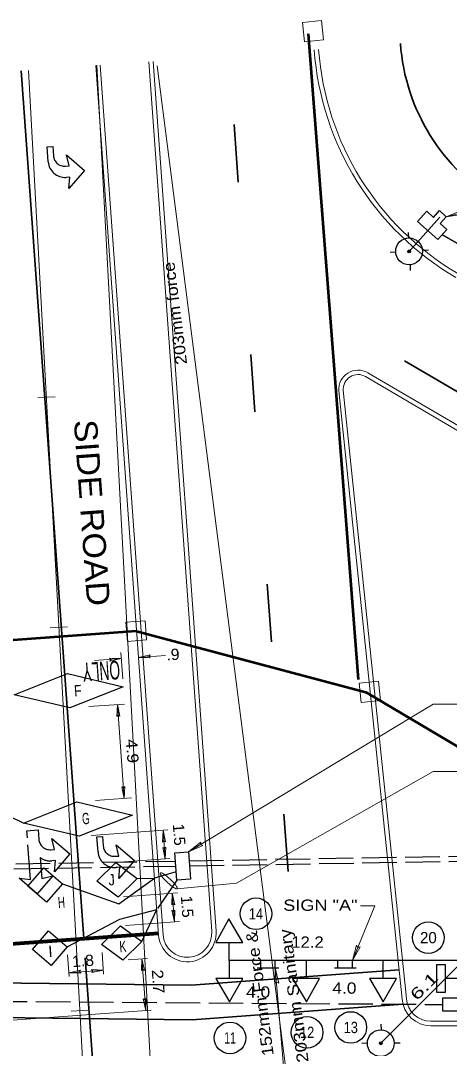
# Model space of a CAD drawing. Extents: x 168203 to 169863, y 223196 to 223870.
# Drawn here: x 168345.6 to 168367.9, y 223652.3 to 223705.8 of the extents above; entities that cross this region are included whole.
import ezdxf
from ezdxf.enums import TextEntityAlignment as Align

# ---------------------------------------------------------------- set-up
doc = ezdxf.new("R2010")
doc.units = 0
doc.header["$LTSCALE"] = 0.3
doc.header["$PDMODE"] = 32
doc.header["$PDSIZE"] = 0.15
doc.linetypes.add('LONG_DASH_SHORT_DASH', pattern=[9.9, 6, -1.2, 1.5, -1.2])
doc.linetypes.add('LONG_DASHED', pattern=[7.5, 6, -1.5])
for name, color, linetype, lineweight in [('1', 7, 'Continuous', 13), ('11', 7, 'Continuous', 13), ('23', 7, 'Continuous', 25), ('31', 7, 'Continuous', 25), ('36', 7, 'Continuous', 35), ('5', 7, 'Continuous', 25), ('7', 7, 'Continuous', 25), ('9', 7, 'Continuous', 13)]:
    doc.layers.add(name, color=color, linetype=linetype, lineweight=lineweight)

msp = doc.modelspace()

# ---------------------------------------------------------------- linework, layer by layer
at = {"layer": '1'}
for p, q in [((168352.2908, 223703.665), (168355.5629, 223658.3883)), ((168352.5202, 223703.6815), (168355.7923, 223658.4049)), ((168349.7975, 223634.2675), (168346.0287, 223703.2124)), ((168352.8001, 223658.1888), (168349.528, 223703.4653)), ((168353.0296, 223658.2052), (168349.7575, 223703.4819)), ((168363.5687, 223687.27), (168399.2919, 223666.2921)), ((168363.6851, 223687.4684), (168399.4139, 223666.4872)), ((168365.473, 223654.8595), (168362.1813, 223686.534)), ((168365.7018, 223654.8832), (168362.4101, 223686.5577)), ((168346.5111, 223686.1736), (168347.4098, 223686.2226)), ((168347.1644, 223674.1914), (168348.0631, 223674.2404)), ((168348.256, 223654.2212), (168349.1547, 223654.2702)), ((168389.7958, 223653.6976), (168366.9691, 223653.6976)), ((168389.7958, 223653.4676), (168366.9691, 223653.4676))]:
    msp.add_line(p, q, dxfattribs=at)
for points in [[(168360.2873, 223705.7061), (168361.2849, 223705.8098), (168361.3886, 223704.8122), (168360.391, 223704.7085)], [(168351.1029, 223674.483), (168352.1033, 223674.5553), (168352.1756, 223673.5549), (168351.1752, 223673.4826)], [(168363.2438, 223671.3005), (168364.2414, 223671.4042), (168364.3451, 223670.4066), (168363.3475, 223670.3029)]]:
    msp.add_lwpolyline(points, close=True, dxfattribs=at)
for centre, radius, start, end in [((168375.8594, 223705.3683), 15, 184.13349, 239.57703), ((168375.8594, 223705.3683), 14.77, 184.13349, 239.57703), ((168363.1787, 223686.6061), 1, 59.57703, 184.13349), ((168363.1787, 223686.6061), 0.77, 59.57703, 184.13349), ((168354.296, 223658.2969), 1.5, 184.13349, 4.13349), ((168354.296, 223658.2969), 1.27, 184.13349, 4.13349), ((168366.9691, 223654.9676), 1.5, 184.13349, 270.00005), ((168366.9691, 223654.9676), 1.27, 184.13349, 270.00005)]:
    msp.add_arc(centre, radius, start, end, dxfattribs=at)
at = {"layer": '1', "lineweight": 35}
msp.add_arc((168375.8594, 223705.3683), 10.5001, 184.13349, 239.57769, dxfattribs=at)
at = {"layer": '11'}
msp.add_line((168367.7738, 223695.5936), (168376.8432, 223697.9525), dxfattribs=at)
msp.add_lwpolyline([(168368.5859, 223695.7021), (168367.7738, 223695.5936), (168368.5336, 223695.9032), (168368.4821, 223695.7778)], close=True, dxfattribs=at)
at = {"layer": '23', "lineweight": 53}
for p, q in [((168363.2123, 223671.494), (168360.5984, 223705.115)), ((168351.6566, 223674.0176), (168339.6878, 223673.1527)), ((168351.6566, 223674.0176), (168363.59, 223670.8389)), ((168363.59, 223670.8389), (168378.9117, 223661.7152))]:
    msp.add_line(p, q, dxfattribs=at)
at = {"layer": '23', "lineweight": 13}
for p, q in [((168357.586, 223554.132), (168349.5897, 223703.4835)), ((168359.4003, 223651.3453), (168352.7333, 223703.4586))]:
    msp.add_line(p, q, dxfattribs=at)
at = {"layer": '31'}
for p, q in [((168365.8391, 223693.7889), (168367.4388, 223695.578)), ((168356.4781, 223656.8676), (168356.4781, 223657.8074)), ((168368.6781, 223656.8676), (168356.4781, 223656.8676)), ((168356.4781, 223656.8676), (168356.4781, 223655.9278)), ((168357.9267, 223656.4839), (168359.0562, 223656.4839)), ((168358.1165, 223656.4839), (168358.1165, 223656.8634)), ((168358.8755, 223656.4839), (168358.8755, 223656.8634)), ((168360.4781, 223656.8676), (168360.4781, 223655.9278)), ((168361.9467, 223656.4888), (168363.0762, 223656.4888)), ((168362.1365, 223656.4888), (168362.1365, 223656.8683)), ((168362.8955, 223656.4888), (168362.8955, 223656.8683)), ((168368.6781, 223656.8676), (168364.3648, 223652.5542)), ((168364.4781, 223656.8676), (168364.4781, 223655.9278)), ((168368.6781, 223655.9278), (168367.7383, 223655.9278))]:
    msp.add_line(p, q, dxfattribs=at)
at = {"layer": '31', "lineweight": 13}
for p in [(168362.8955, 223656.8683), (168363.3021, 223659.7147)]:
    msp.add_line(p, (168364.0608, 223659.7147), dxfattribs=at)
at = {"layer": '31', "linetype": 'LONG_DASH_SHORT_DASH'}
for points in [[(168356.46, 223659.0272), (168355.7733, 223657.8074), (168356.4781, 223657.8074), (168357.1829, 223657.8074)], [(168367.2685, 223656.6417), (168367.2685, 223655.223), (168367.7383, 223655.223), (168367.7383, 223656.6417)], [(168356.4962, 223654.708), (168357.1829, 223655.9278), (168356.4781, 223655.9278), (168355.7733, 223655.9278)], [(168360.4962, 223654.708), (168361.1829, 223655.9278), (168360.4781, 223655.9278), (168359.7733, 223655.9278)], [(168364.4962, 223654.708), (168365.1829, 223655.9278), (168364.4781, 223655.9278), (168363.7733, 223655.9278)]]:
    msp.add_lwpolyline(points, close=True, dxfattribs=at)
at = {"layer": '31', "lineweight": 13}
for points in [[(168363.2956, 223657.5833), (168362.8955, 223656.8683), (168363.1033, 223657.662), (168363.1728, 223657.5456)], [(168358.8429, 223655.6652), (168358.8755, 223656.4839), (168359.05, 223655.6822), (168358.9353, 223655.7544)]]:
    msp.add_lwpolyline(points, close=True, dxfattribs=at)
msp.add_lwpolyline([(168358.5538, 223651.1547), (168359.3125, 223651.1547), (168358.8755, 223656.4839)], dxfattribs=at)
at = {"layer": '31'}
for centre in [(168357.8675, 223659.2956), (168366.8425, 223658.0542), (168360.5298, 223653.1218), (168362.8039, 223653.376), (168356.52, 223652.8356)]:
    msp.add_circle(centre, 0.8236, dxfattribs=at)
at = {"layer": '36'}
for p, q in [((168348.9037, 223658.0067), (168345.6389, 223703.1842)), ((168356.7281, 223700.3938), (168356.9443, 223697.4016)), ((168357.5931, 223688.425), (168357.8093, 223685.4328)), ((168365.5999, 223688.0978), (168400.2978, 223667.7219)), ((168358.4581, 223676.4562), (168358.6743, 223673.464)), ((168359.323, 223664.4874), (168359.5393, 223661.4952)), ((168349.5082, 223649.6433), (168348.9759, 223657.0092)), ((168354.5482, 223653.7832), (168365.5163, 223654.5943)), ((168331.8751, 223654.0405), (168354.5482, 223653.7832))]:
    msp.add_line(p, q, dxfattribs=at)
at = {"layer": '36', "lineweight": 80}
msp.add_line((168336.8478, 223657.135), (168352.7935, 223658.2879), dxfattribs=at)
at = {"layer": '36', "linetype": 'LONG_DASH_SHORT_DASH', "lineweight": 25}
for points in [[(168347.0511, 223698.4569), (168346.9949, 223699.2352), (168347.2867, 223699.2563), (168347.3219, 223698.7699)], [(168347.9477, 223698.2284), (168348.1423, 223698.2425), (168348.0029, 223698.8191), (168348.9417, 223698.0069), (168348.1295, 223697.0681), (168348.1845, 223697.6588), (168347.9899, 223697.6447)], [(168346.635, 223662.2303), (168346.7145, 223661.1318), (168347.2911, 223661.2712), (168346.4789, 223660.3324), (168345.5401, 223661.1446), (168346.1308, 223661.0896), (168345.9479, 223663.6189), (168346.5316, 223663.6611), (168346.5668, 223663.1746)], [(168347.1926, 223662.6332), (168347.3872, 223662.6472), (168347.2478, 223663.2239)], [(168347.2478, 223663.2239), (168348.1866, 223662.4117), (168347.3744, 223661.4728), (168347.4294, 223662.0636), (168347.2348, 223662.0495)], [(168349.6464, 223662.519), (168349.5902, 223663.2973), (168349.882, 223663.3184), (168349.9172, 223662.832)], [(168350.543, 223662.2905), (168350.7376, 223662.3046), (168350.5982, 223662.8812), (168351.537, 223662.069), (168350.7248, 223661.1302), (168350.7798, 223661.7209), (168350.5852, 223661.7068)]]:
    msp.add_lwpolyline(points, dxfattribs=at)
at = {"layer": '36'}
msp.add_lwpolyline([(168335.3225, 223655.8015), (168354.4921, 223655.584), (168365.3145, 223656.3843)], dxfattribs=at)
at = {"layer": '36', "linetype": 'LONG_DASH_SHORT_DASH', "lineweight": 25}
for centre, radius, start in [((168347.9056, 223698.8121), 0.5852, 184.13538), ((168347.9267, 223698.5203), 0.8778, 184.13538), ((168347.1505, 223663.2169), 0.5852, 184.13538), ((168350.522, 223662.5824), 0.8778, 184.13538), ((168350.5009, 223662.8742), 0.5852, 184.13538), ((168347.1716, 223662.925), 0.8778, 232.32592)]:
    msp.add_arc(centre, radius, start, 274.13538, dxfattribs=at)
at = {"layer": '5'}
for p, q in [((168366.7534, 223695.8757), (168367.1037, 223695.5625)), ((168367.7738, 223695.5936), (168367.4607, 223695.2433)), ((168367.4607, 223695.2433), (168367.8043, 223694.9361)), ((168345.7614, 223664.0228), (168340.154, 223666.695)), ((168351.6844, 223661.1422), (168352.5856, 223661.1565)), ((168351.9222, 223657.8508), (168352.7043, 223659.5146))]:
    msp.add_line(p, q, dxfattribs=at)
at = {"layer": '5', "linetype": 'LONG_DASHED'}
for p, q in [((168367.5664, 223694.67), (168407.4793, 223671.2335)), ((168338.6144, 223661.7866), (168353.6802, 223662.0439)), ((168354.3859, 223662.0559), (168368.3631, 223662.2946)), ((168354.4049, 223661.7919), (168368.3905, 223662.0308)), ((168338.522, 223661.5206), (168353.6992, 223661.7798)), ((168353.7213, 223661.474), (168352.5856, 223661.1565)), ((168353.7518, 223661.0521), (168352.7043, 223659.5146)), ((168330.6585, 223654.8306), (168367.6027, 223654.5745))]:
    msp.add_line(p, q, dxfattribs=at)
at = {"layer": '5', "lineweight": 13}
for p, q in [((168350.8575, 223672.5844), (168349.4622, 223672.4836)), ((168350.934, 223671.5245), (168350.834, 223672.9104)), ((168353.1504, 223672.75), (168351.7551, 223672.6492)), ((168351.0284, 223670.2182), (168349.1684, 223670.0838)), ((168351.0081, 223665.304), (168350.655, 223670.1912)), ((168351.3816, 223665.331), (168349.5216, 223665.1966)), ((168353.2748, 223663.6634), (168349.2948, 223663.3756)), ((168353.1377, 223662.1496), (168353.0296, 223663.6457)), ((168353.383, 223662.1673), (168350.9998, 223661.995)), ((168353.7814, 223660.3914), (168350.9703, 223660.1882)), ((168353.6209, 223658.8758), (168353.5128, 223660.372)), ((168353.8895, 223658.8952), (168351.0784, 223658.6921)), ((168348.1443, 223656.0303), (168348.0629, 223657.1557)), ((168349.9391, 223656.1602), (168349.8577, 223657.2856)), ((168352.22, 223656.9699), (168351.2081, 223656.8968)), ((168352.1266, 223654.2638), (168351.9326, 223656.9491)), ((168349.9248, 223656.3583), (168348.13, 223656.2288)), ((168352.414, 223654.2846), (168341.1099, 223653.4677))]:
    msp.add_line(p, q, dxfattribs=at)
at = {"layer": '5'}
for points in [[(168367.8043, 223694.9361), (168367.3285, 223694.4039), (168366.2776, 223695.3435), (168366.7534, 223695.8757)], [(168367.1037, 223695.5625), (168367.4168, 223695.9127), (168367.7738, 223695.5936)], [(168347.7951, 223660.861), (168350.7276, 223659.8149), (168352.5856, 223661.1565)], [(168348.0329, 223657.5698), (168350.7848, 223659.021), (168352.7043, 223659.5146)]]:
    msp.add_lwpolyline(points, dxfattribs=at)
at = {"layer": '5', "lineweight": 13}
for points in [[(168350.2438, 223672.6148), (168350.8575, 223672.5844), (168350.2549, 223672.4594), (168350.31, 223672.5449)], [(168352.3688, 223672.6188), (168351.7551, 223672.6492), (168352.3577, 223672.7742), (168352.3026, 223672.6887)], [(168350.6246, 223669.5775), (168350.655, 223670.1912), (168350.78, 223669.5886), (168350.6945, 223669.6437)], [(168351.0385, 223665.9177), (168351.0081, 223665.304), (168350.8831, 223665.9066), (168350.9686, 223665.8515)], [(168352.9992, 223663.032), (168353.0296, 223663.6457), (168353.1546, 223663.0431), (168353.0691, 223663.0982)], [(168353.1681, 223662.7633), (168353.1377, 223662.1496), (168353.0127, 223662.7522), (168353.0982, 223662.6971)], [(168353.4824, 223659.7583), (168353.5128, 223660.372), (168353.6378, 223659.7694), (168353.5523, 223659.8245)], [(168353.6513, 223659.4895), (168353.6209, 223658.8758), (168353.4959, 223659.4784), (168353.5814, 223659.4233)], [(168351.9022, 223656.3354), (168351.9326, 223656.9491), (168352.0576, 223656.3465), (168351.9721, 223656.4016)], [(168348.7437, 223656.1984), (168348.13, 223656.2288), (168348.7326, 223656.3538), (168348.6775, 223656.2683)], [(168349.3111, 223656.3887), (168349.9248, 223656.3583), (168349.3222, 223656.2333), (168349.3773, 223656.3188)], [(168352.157, 223654.8775), (168352.1266, 223654.2638), (168352.0016, 223654.8664), (168352.0871, 223654.8113)]]:
    msp.add_lwpolyline(points, close=True, dxfattribs=at)
at = {"layer": '5'}
for points in [[(168345.2785, 223670.7052), (168348.0562, 223671.8082), (168350.9636, 223671.1158), (168348.186, 223670.0128)], [(168345.7614, 223664.0228), (168348.5391, 223665.1258), (168351.4465, 223664.4334), (168348.6689, 223663.3304)], [(168354.3525, 223662.5179), (168354.4547, 223661.1029), (168353.7518, 223661.0521), (168353.6496, 223662.4671)], [(168349.5899, 223660.9909), (168350.5722, 223661.9642), (168351.6844, 223661.1422), (168350.702, 223660.1688)], [(168345.9998, 223660.7313), (168346.8325, 223661.6938), (168347.7951, 223660.861), (168346.9623, 223659.8984)], [(168349.8277, 223657.6995), (168350.81, 223658.6728), (168351.9222, 223657.8508), (168350.9398, 223656.8774)], [(168346.2376, 223657.4401), (168347.0703, 223658.4026), (168348.0329, 223657.5698), (168347.2001, 223656.6072)], [(168369.0214, 223654.2176), (168367.6027, 223654.2176), (168367.6027, 223654.9224), (168369.0214, 223654.9224)]]:
    msp.add_lwpolyline(points, close=True, dxfattribs=at)
at = {"layer": '7'}
for p, q in [((168365.7901, 223694.7781), (168365.8125, 223694.4914)), ((168365.1373, 223693.7497), (168364.8506, 223693.7273)), ((168366.8471, 223693.8452), (168366.5281, 223693.8274)), ((168365.8903, 223693.1006), (168365.9015, 223692.7877)), ((168364.3711, 223653.5446), (168364.3775, 223653.2571)), ((168363.6619, 223652.5542), (168363.3744, 223652.5478)), ((168365.3744, 223652.5542), (168365.0549, 223652.5542))]:
    msp.add_line(p, q, dxfattribs=at)
for centre in [(168365.8357, 223693.7919), (168364.3616, 223652.5574)]:
    msp.add_circle(centre, 0.6965, dxfattribs=at)
for p in [(168365.8391, 223693.7889), (168364.3648, 223652.5542)]:
    msp.add_point(p, dxfattribs=at)
at = {"layer": '9'}
for p, q in [((168354.3616, 223662.5186), (168367.0853, 223670.2051)), ((168389.9644, 223670.2051), (168367.0853, 223670.2051)), ((168389.9644, 223666.7051), (168367.0853, 223666.7051))]:
    msp.add_line(p, q, dxfattribs=at)
msp.add_lwpolyline([(168353.7695, 223660.6006), (168356.8513, 223660.8997), (168367.0853, 223666.7051)], dxfattribs=at)
msp.add_lwpolyline([(168355.1091, 223662.8541), (168354.3616, 223662.5186), (168355.0017, 223663.0319), (168354.9881, 223662.8971)], close=True, dxfattribs=at)
msp.add_ellipse((168353.3324, 223661.0127), major_axis=(-0.4371, 0.4121), ratio=0.187826, dxfattribs=at)

# ---------------------------------------------------------------- texts
at = {"layer": '1', "width": 1.1}
msp.add_text('SIDE ROAD', height=1.202, rotation=274.133, dxfattribs=at).set_placement((168348.7371, 223680.1369), align=Align.CENTER)
at = {"layer": '23'}
for s, rotation, width, p in [('203mm force', 97.198, 1.15, (168353.9495, 223690.5999)), ('152mm Force & ', 97.692, 1.15, (168358.3408, 223655.3191)), ('203mm Sanitary', 97.692, 1.2, (168360.1428, 223655.0662))]:
    msp.add_text(s, height=0.6, rotation=rotation, dxfattribs=dict(at, width=width)).set_placement(p, align=Align.CENTER)
at = {"layer": '31'}
for s, width, p in [('SIGN "A"', 1.2, (168361.2205, 223659.4509)), ('14', 0.85, (168357.8675, 223659.002)), ('12.2', 1.1, (168360.5519, 223657.5294)), ('4.0', 1.15, (168357.9811, 223654.9306)), ('4.0', 1.15, (168362.4698, 223655.1354)), ('12', 0.85, (168360.5298, 223652.8282)), ('13', 0.85, (168362.8039, 223653.0824)), ('11', 0.7, (168356.52, 223652.542))]:
    msp.add_text(s, height=0.5873, dxfattribs=dict(at, width=width)).set_placement(p, align=Align.CENTER)
msp.add_text('20', height=0.5873, dxfattribs=at).set_placement((168366.8426, 223657.7606), align=Align.CENTER)
at = {"layer": '31', "width": 1.5}
msp.add_text('6.1', height=0.5873, rotation=45.001, dxfattribs=at).set_placement((168366.8232, 223655.3188), align=Align.CENTER)
at = {"layer": '36', "width": 0.55}
msp.add_text('ONLY', height=0.9715, rotation=183.898, dxfattribs=at).set_placement((168349.7856, 223672.4202), align=Align.CENTER)
at = {"layer": '5'}
for s, rotation, width, p in [('.9', 4.134, 1.05, (168353.567, 223672.5045)), ('F', 4.133, 0.8, (168348.6145, 223670.623)), ('4.9', 274.134, 1.15, (168351.1406, 223667.7482)), ('G', 4.133, 0.65, (168349.0347, 223663.9642)), ('1.5', 274.132, 1.05, (168353.5776, 223663.3972)), ('J', 4.133, 0.85, (168350.3729, 223660.7776)), ('H', 4.133, 0.65, (168347.7629, 223659.5998)), ('1.5', 274.132, 1.05, (168353.9967, 223659.6493)), ('K', 4.133, 0.7, (168350.9616, 223657.305)), ('1.8', 4.132, 1.05, (168348.8834, 223656.5553)), ('2.7', 274.132, 1.15, (168352.4867, 223655.7443))]:
    msp.add_text(s, height=0.5873, rotation=rotation, dxfattribs=dict(at, width=width)).set_placement(p, align=Align.CENTER)
msp.add_text('I', height=0.5873, rotation=4.133, dxfattribs=at).set_placement((168347.1897, 223657.0443), align=Align.CENTER)

doc.saveas('drawing.dxf')
